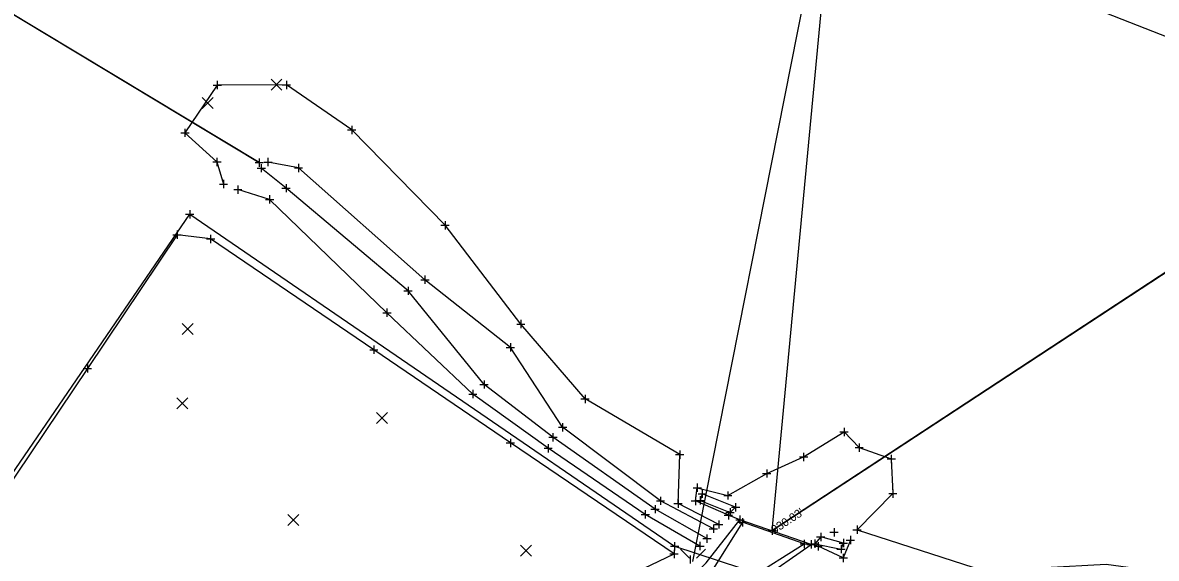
# Model space of a CAD drawing. Extents: x 2331247 to 2333939, y 279314 to 282014.
# Drawn here: x 2332516.5 to 2332654, y 280471.6 to 280536.5 of the extents above; entities that cross this region are included whole.
import ezdxf

# ---------------------------------------------------------------- set-up
doc = ezdxf.new("R2010")
doc.units = 0
for name, color, linetype in [('DR_X_Drive_Pipe', 7, 'Continuous'), ('DR_X_Headwall', 7, 'Continuous'), ('DR_X_Storm_Sewer', 7, 'Continuous'), ('HY_X_Water_Edge', 7, 'Continuous'), ('RD_X_Fence', 7, 'Continuous'), ('SC_Scratch1', 7, 'Continuous'), ('Stream 1', 7, 'Continuous'), ('SV_Observation', 7, 'Continuous'), ('SV_X_Break_Lines', 7, 'Continuous'), ('SV_X_Control_Cells_Found', 7, 'Continuous'), ('SV_X_Random_Point', 7, 'Continuous'), ('UT_X_Overhead_Telecom', 7, 'Continuous')]:
    doc.layers.add(name, color=color, linetype=linetype)

msp = doc.modelspace()

# ---------------------------------------------------------------- linework, layer by layer
msp.add_lwpolyline([(2332817.33, 280612.66), (2332607.42, 280474.92)])
at = {"layer": 'DR_X_Drive_Pipe'}
msp.add_lwpolyline([(2332545.21, 280519.51), (2332447.92, 280578.06)], dxfattribs=at)
at = {"layer": 'DR_X_Headwall'}
for points in [[(2332602.98, 280477.75), (2332598.92, 280479.38), (2332598.67, 280478.58), (2332602.3, 280477.12)], [(2332615.76, 280472.68), (2332616.05, 280473.41), (2332613.3, 280474.15), (2332612.59, 280473.32)]]:
    msp.add_lwpolyline(points, close=True, dxfattribs=at)
at = {"layer": 'DR_X_Storm_Sewer'}
for p, q in [((2332607.42, 280474.92), (2332817.33, 280612.66)), ((2332447.92, 280578.06), (2332545.21, 280519.51))]:
    msp.add_line(p, q, dxfattribs=at)
at = {"layer": 'HY_X_Water_Edge'}
for points in [[(2332363.34, 280175.46), (2332389.42, 280200.76), (2332413.43, 280199.51), (2332417.58, 280206.07), (2332416.16, 280218.98), (2332423.66, 280245.69), (2332431.91, 280271.77), (2332444.8, 280293.01), (2332458.58, 280309.27), (2332481.85, 280326.75), (2332494.02, 280345.7), (2332502.42, 280362.31), (2332517.37, 280370.05), (2332526.14, 280366.88), (2332534.75, 280384.03), (2332544.11, 280395.57), (2332549.43, 280417.73), (2332557.29, 280431.22), (2332566.01, 280443.67), (2332582.71, 280453.54), (2332593.15, 280464.65), (2332599.39, 280471.03), (2332603.51, 280476.23)], [(2332394.74, 280194.82), (2332415.54, 280196.86), (2332423.02, 280200.68), (2332423.85, 280205.22), (2332421.05, 280220.72), (2332429.21, 280245.01), (2332436.82, 280271.58), (2332449.74, 280290.96), (2332464.91, 280306.08), (2332482.64, 280321.13), (2332499.76, 280345.28), (2332505.68, 280360.47), (2332506.64, 280362.04), (2332519.58, 280364.48), (2332528.79, 280364.13), (2332536.96, 280380.5), (2332548.69, 280396.62), (2332555.94, 280412.9), (2332564.08, 280431.96), (2332575.6, 280441.74), (2332591.29, 280450.67), (2332604.28, 280463.06), (2332605.89, 280468.85), (2332612.13, 280473.25)]]:
    msp.add_lwpolyline(points, dxfattribs=at)
at = {"layer": 'RD_X_Fence'}
msp.add_lwpolyline([(2332471.27, 280418.89), (2332503.51, 280464.65), (2332536.8, 280513.25), (2332595.58, 280473.01), (2332611.71, 280467.72), (2332629.37, 280467.72), (2332688.32, 280457.09), (2332754.9, 280426.71), (2332807.86, 280397.34), (2332857.71, 280364.51), (2332902.55, 280327.37), (2332945.19, 280285.57), (2332980.98, 280237.15), (2333013.15, 280194.42), (2333002.94, 280179.22), (2332931.31, 280144.84)], dxfattribs=at)
at = {"layer": 'SC_Scratch1'}
for p, q in [((2332607.42, 280475.42), (2332607.42, 280474.42)), ((2332606.92, 280474.92), (2332607.92, 280474.92)), ((2332607.42, 280474.92), (2332607.42, 280474.92))]:
    msp.add_line(p, q, dxfattribs=at)
at = {"layer": 'Stream 1'}
for p, q in [((2332539.64, 280528.91), (2332540.64, 280528.91)), ((2332540.14, 280529.41), (2332540.14, 280528.41)), ((2332540.14, 280528.91), (2332540.14, 280528.91)), ((2332548.02, 280528.92), (2332549.02, 280528.92)), ((2332548.52, 280529.42), (2332548.52, 280528.42)), ((2332548.52, 280528.92), (2332548.52, 280528.92)), ((2332536.21, 280523.62), (2332536.21, 280522.62)), ((2332555.93, 280523.47), (2332556.93, 280523.47)), ((2332556.43, 280523.97), (2332556.43, 280522.97)), ((2332556.43, 280523.47), (2332556.43, 280523.47)), ((2332535.71, 280523.12), (2332536.71, 280523.12)), ((2332536.21, 280523.12), (2332536.21, 280523.12)), ((2332539.59, 280519.59), (2332540.59, 280519.59)), ((2332540.09, 280520.09), (2332540.09, 280519.09)), ((2332540.09, 280519.59), (2332540.09, 280519.59)), ((2332544.71, 280519.51), (2332545.71, 280519.51)), ((2332545.21, 280520.01), (2332545.21, 280519.01)), ((2332545.21, 280519.51), (2332545.21, 280519.51)), ((2332545.47, 280519.34), (2332545.47, 280518.34)), ((2332545.78, 280519.58), (2332546.78, 280519.58)), ((2332546.28, 280520.08), (2332546.28, 280519.08)), ((2332546.28, 280519.58), (2332546.28, 280519.58)), ((2332549.98, 280519.37), (2332549.98, 280518.37)), ((2332544.97, 280518.84), (2332545.97, 280518.84)), ((2332545.47, 280518.84), (2332545.47, 280518.84)), ((2332549.48, 280518.87), (2332550.48, 280518.87)), ((2332549.98, 280518.87), (2332549.98, 280518.87)), ((2332540.39, 280516.92), (2332541.39, 280516.92)), ((2332540.89, 280517.42), (2332540.89, 280516.42)), ((2332540.89, 280516.92), (2332540.89, 280516.92)), ((2332542.63, 280516.74), (2332542.63, 280515.74)), ((2332548.47, 280516.92), (2332548.47, 280515.92)), ((2332542.13, 280516.24), (2332543.13, 280516.24)), ((2332542.63, 280516.24), (2332542.63, 280516.24)), ((2332546.48, 280515.55), (2332546.48, 280514.55)), ((2332547.97, 280516.42), (2332548.97, 280516.42)), ((2332548.47, 280516.42), (2332548.47, 280516.42)), ((2332545.98, 280515.05), (2332546.98, 280515.05)), ((2332546.48, 280515.05), (2332546.48, 280515.05)), ((2332536.3, 280513.25), (2332537.3, 280513.25)), ((2332536.8, 280513.75), (2332536.8, 280512.75)), ((2332536.8, 280513.25), (2332536.8, 280513.25)), ((2332567.75, 280512.42), (2332567.75, 280511.42)), ((2332535.26, 280511.27), (2332535.26, 280510.27)), ((2332567.25, 280511.92), (2332568.25, 280511.92)), ((2332567.75, 280511.92), (2332567.75, 280511.92)), ((2332534.76, 280510.77), (2332535.76, 280510.77)), ((2332535.26, 280510.77), (2332535.26, 280510.77)), ((2332538.83, 280510.27), (2332539.83, 280510.27)), ((2332539.33, 280510.77), (2332539.33, 280509.77)), ((2332539.33, 280510.27), (2332539.33, 280510.27)), ((2332565.31, 280505.82), (2332565.31, 280504.82)), ((2332563.26, 280504.47), (2332563.26, 280503.47)), ((2332564.81, 280505.32), (2332565.81, 280505.32)), ((2332565.31, 280505.32), (2332565.31, 280505.32)), ((2332562.76, 280503.97), (2332563.76, 280503.97)), ((2332563.26, 280503.97), (2332563.26, 280503.97)), ((2332560.7, 280501.82), (2332560.7, 280500.82)), ((2332560.2, 280501.32), (2332561.2, 280501.32)), ((2332560.7, 280501.32), (2332560.7, 280501.32)), ((2332576.94, 280500.45), (2332576.94, 280499.45)), ((2332576.44, 280499.95), (2332577.44, 280499.95)), ((2332576.94, 280499.95), (2332576.94, 280499.95)), ((2332559.12, 280497.33), (2332559.12, 280496.33)), ((2332575.67, 280497.62), (2332575.67, 280496.62)), ((2332558.62, 280496.83), (2332559.62, 280496.83)), ((2332559.12, 280496.83), (2332559.12, 280496.83)), ((2332575.17, 280497.12), (2332576.17, 280497.12)), ((2332575.67, 280497.12), (2332575.67, 280497.12)), ((2332523.89, 280494.56), (2332524.89, 280494.56)), ((2332524.39, 280495.06), (2332524.39, 280494.06)), ((2332524.39, 280494.56), (2332524.39, 280494.56)), ((2332571.12, 280491.97), (2332571.12, 280490.97)), ((2332571.98, 280492.62), (2332572.98, 280492.62)), ((2332572.48, 280493.12), (2332572.48, 280492.12)), ((2332572.48, 280492.62), (2332572.48, 280492.62)), ((2332570.62, 280491.47), (2332571.62, 280491.47)), ((2332571.12, 280491.47), (2332571.12, 280491.47)), ((2332584.22, 280490.87), (2332585.22, 280490.87)), ((2332584.72, 280491.37), (2332584.72, 280490.37)), ((2332584.72, 280490.87), (2332584.72, 280490.87)), ((2332582.01, 280487.94), (2332582.01, 280486.94)), ((2332580.83, 280486.73), (2332580.83, 280485.73)), ((2332581.51, 280487.44), (2332582.51, 280487.44)), ((2332582.01, 280487.44), (2332582.01, 280487.44)), ((2332615.63, 280486.87), (2332616.63, 280486.87)), ((2332616.13, 280487.37), (2332616.13, 280486.37)), ((2332616.13, 280486.87), (2332616.13, 280486.87)), ((2332575.17, 280485.54), (2332576.17, 280485.54)), ((2332575.67, 280486.04), (2332575.67, 280485.04)), ((2332575.67, 280485.54), (2332575.67, 280485.54)), ((2332580.25, 280485.4), (2332580.25, 280484.4)), ((2332580.33, 280486.23), (2332581.33, 280486.23)), ((2332580.83, 280486.23), (2332580.83, 280486.23)), ((2332617.46, 280484.97), (2332618.46, 280484.97)), ((2332617.96, 280485.47), (2332617.96, 280484.47)), ((2332617.96, 280484.97), (2332617.96, 280484.97)), ((2332579.75, 280484.9), (2332580.75, 280484.9)), ((2332580.25, 280484.9), (2332580.25, 280484.9)), ((2332595.7, 280484.13), (2332596.7, 280484.13)), ((2332596.2, 280484.63), (2332596.2, 280483.63)), ((2332596.2, 280484.13), (2332596.2, 280484.13)), ((2332610.73, 280483.84), (2332611.73, 280483.84)), ((2332611.23, 280484.34), (2332611.23, 280483.34)), ((2332611.23, 280483.84), (2332611.23, 280483.84)), ((2332621.36, 280483.6), (2332622.36, 280483.6)), ((2332621.86, 280484.1), (2332621.86, 280483.1)), ((2332621.86, 280483.6), (2332621.86, 280483.6)), ((2332606.75, 280482.34), (2332606.75, 280481.34)), ((2332606.25, 280481.84), (2332607.25, 280481.84)), ((2332606.75, 280481.84), (2332606.75, 280481.84)), ((2332597.83, 280480.11), (2332598.83, 280480.11)), ((2332598.33, 280480.61), (2332598.33, 280479.61)), ((2332598.33, 280480.11), (2332598.33, 280480.11)), ((2332598.92, 280479.88), (2332598.92, 280478.88)), ((2332602.04, 280479.67), (2332602.04, 280478.67)), ((2332622.04, 280479.9), (2332622.04, 280478.9)), ((2332593.37, 280478.52), (2332594.37, 280478.52)), ((2332593.87, 280479.02), (2332593.87, 280478.02)), ((2332593.87, 280478.52), (2332593.87, 280478.52)), ((2332595.5, 280478.19), (2332596.5, 280478.19)), ((2332596, 280478.69), (2332596, 280477.69)), ((2332596, 280478.19), (2332596, 280478.19)), ((2332597.61, 280478.51), (2332598.61, 280478.51)), ((2332598.11, 280479.01), (2332598.11, 280478.01)), ((2332598.11, 280478.51), (2332598.11, 280478.51)), ((2332598.17, 280478.58), (2332599.17, 280478.58)), ((2332598.42, 280479.38), (2332599.42, 280479.38)), ((2332598.67, 280479.08), (2332598.67, 280478.08)), ((2332598.67, 280478.58), (2332598.67, 280478.58)), ((2332598.92, 280479.38), (2332598.92, 280479.38)), ((2332601.54, 280479.17), (2332602.54, 280479.17)), ((2332602.04, 280479.17), (2332602.04, 280479.17)), ((2332602.98, 280478.25), (2332602.98, 280477.25)), ((2332621.54, 280479.4), (2332622.54, 280479.4)), ((2332622.04, 280479.4), (2332622.04, 280479.4)), ((2332591.53, 280476.88), (2332592.53, 280476.88)), ((2332592.03, 280477.38), (2332592.03, 280476.38)), ((2332592.03, 280476.88), (2332592.03, 280476.88)), ((2332592.71, 280477.51), (2332593.71, 280477.51)), ((2332593.21, 280478.01), (2332593.21, 280477.01)), ((2332593.21, 280477.51), (2332593.21, 280477.51)), ((2332601.61, 280476.78), (2332602.61, 280476.78)), ((2332601.8, 280477.12), (2332602.8, 280477.12)), ((2332602.11, 280477.28), (2332602.11, 280476.28)), ((2332602.11, 280476.78), (2332602.11, 280476.78)), ((2332602.3, 280477.62), (2332602.3, 280476.62)), ((2332602.3, 280477.12), (2332602.3, 280477.12)), ((2332602.48, 280477.75), (2332603.48, 280477.75)), ((2332602.98, 280477.75), (2332602.98, 280477.75)), ((2332603.51, 280476.73), (2332603.51, 280475.73)), ((2332600.28, 280475.64), (2332600.28, 280474.64)), ((2332600.43, 280475.66), (2332601.43, 280475.66)), ((2332600.93, 280476.16), (2332600.93, 280475.16)), ((2332600.93, 280475.66), (2332600.93, 280475.66)), ((2332603.01, 280476.23), (2332604.01, 280476.23)), ((2332603.31, 280475.92), (2332604.31, 280475.92)), ((2332603.51, 280476.23), (2332603.51, 280476.23)), ((2332603.81, 280476.42), (2332603.81, 280475.42)), ((2332603.81, 280475.92), (2332603.81, 280475.92)), ((2332617.7, 280475.52), (2332617.7, 280474.52)), ((2332599.01, 280473.95), (2332600.01, 280473.95)), ((2332599.51, 280474.45), (2332599.51, 280473.45)), ((2332599.51, 280473.95), (2332599.51, 280473.95)), ((2332599.78, 280475.14), (2332600.78, 280475.14)), ((2332600.28, 280475.14), (2332600.28, 280475.14)), ((2332612.8, 280474.15), (2332613.8, 280474.15)), ((2332613.3, 280474.65), (2332613.3, 280473.65)), ((2332613.3, 280474.15), (2332613.3, 280474.15)), ((2332614.42, 280474.72), (2332615.42, 280474.72)), ((2332614.92, 280475.22), (2332614.92, 280474.22)), ((2332614.92, 280474.72), (2332614.92, 280474.72)), ((2332616.05, 280473.91), (2332616.05, 280472.91)), ((2332616.89, 280474.27), (2332616.89, 280473.27)), ((2332617.2, 280475.02), (2332618.2, 280475.02)), ((2332617.7, 280475.02), (2332617.7, 280475.02)), ((2332595.08, 280473.01), (2332596.08, 280473.01)), ((2332595.52, 280472.59), (2332595.52, 280471.59)), ((2332595.58, 280473.51), (2332595.58, 280472.51)), ((2332595.58, 280473.01), (2332595.58, 280473.01)), ((2332598.16, 280473.04), (2332599.16, 280473.04)), ((2332598.66, 280473.54), (2332598.66, 280472.54)), ((2332598.66, 280473.04), (2332598.66, 280473.04)), ((2332610.79, 280473.3), (2332611.79, 280473.3)), ((2332611.29, 280473.8), (2332611.29, 280472.8)), ((2332611.29, 280473.3), (2332611.29, 280473.3)), ((2332611.63, 280473.25), (2332612.63, 280473.25)), ((2332612.09, 280473.32), (2332613.09, 280473.32)), ((2332612.13, 280473.75), (2332612.13, 280472.75)), ((2332612.13, 280473.25), (2332612.13, 280473.25)), ((2332612.49, 280473.02), (2332613.49, 280473.02)), ((2332612.59, 280473.82), (2332612.59, 280472.82)), ((2332612.59, 280473.32), (2332612.59, 280473.32)), ((2332612.99, 280473.52), (2332612.99, 280472.52)), ((2332612.99, 280473.02), (2332612.99, 280473.02)), ((2332615.26, 280472.68), (2332616.26, 280472.68)), ((2332615.55, 280473.41), (2332616.55, 280473.41)), ((2332615.76, 280473.18), (2332615.76, 280472.18)), ((2332615.76, 280472.68), (2332615.76, 280472.68)), ((2332616.05, 280473.41), (2332616.05, 280473.41)), ((2332616.39, 280473.77), (2332617.39, 280473.77)), ((2332616.89, 280473.77), (2332616.89, 280473.77)), ((2332595.02, 280472.09), (2332596.02, 280472.09)), ((2332595.52, 280472.09), (2332595.52, 280472.09)), ((2332597.47, 280471.91), (2332597.47, 280470.91)), ((2332615.53, 280471.61), (2332616.53, 280471.61)), ((2332616.03, 280472.11), (2332616.03, 280471.11)), ((2332616.03, 280471.61), (2332616.03, 280471.61))]:
    msp.add_line(p, q, dxfattribs=at)
at = {"layer": 'SV_Observation'}
for p in [(2332597.8, 280471.17), (2332607.42, 280474.92)]:
    msp.add_line(p, (2332615.53, 280560.63), dxfattribs=at)
at = {"layer": 'SV_X_Break_Lines'}
for points in [[(2332600.93, 280475.66), (2332596, 280478.19), (2332596.2, 280484.13), (2332584.72, 280490.87), (2332576.94, 280499.95), (2332567.75, 280511.92), (2332556.43, 280523.47), (2332548.52, 280528.92), (2332540.14, 280528.91), (2332536.21, 280523.12), (2332540.09, 280519.59), (2332540.89, 280516.92)], [(2332600.28, 280475.14), (2332593.87, 280478.52), (2332582.01, 280487.44), (2332575.67, 280497.12), (2332565.31, 280505.32), (2332549.98, 280518.87), (2332546.28, 280519.58)], [(2332599.51, 280473.95), (2332593.21, 280477.51), (2332580.83, 280486.23), (2332572.48, 280492.62), (2332563.26, 280503.97), (2332548.47, 280516.42), (2332545.47, 280518.84)], [(2332598.66, 280473.04), (2332592.03, 280476.88), (2332580.25, 280484.9), (2332571.12, 280491.47), (2332560.7, 280501.32), (2332546.48, 280515.05), (2332542.63, 280516.24)], [(2332490.07, 280356.61), (2332496.61, 280366.64), (2332531.85, 280411.22), (2332542.52, 280423.44), (2332554.14, 280437.04), (2332563.39, 280446.89), (2332573.43, 280455.89), (2332581.66, 280460.13), (2332580.9, 280465.12), (2332595.52, 280472.09), (2332575.67, 280485.54), (2332559.12, 280496.83), (2332539.33, 280510.27), (2332535.26, 280510.77), (2332524.39, 280494.56), (2332508.81, 280471.4), (2332491.31, 280445.61), (2332478.44, 280427.4)], [(2332612.99, 280473.02), (2332612.13, 280473.25), (2332603.51, 280476.23), (2332602.11, 280476.78), (2332598.11, 280478.51), (2332598.33, 280480.11), (2332602.04, 280479.17), (2332606.75, 280481.84), (2332611.23, 280483.84), (2332616.13, 280486.87), (2332617.96, 280484.97), (2332621.86, 280483.6), (2332622.04, 280479.4), (2332617.7, 280475.02), (2332633.12, 280470.04), (2332647.91, 280470.83), (2332665.65, 280468.41)], [(2332536.84, 280381.28), (2332548.1, 280396.91), (2332552.36, 280407.18), (2332554.61, 280413.48), (2332563.08, 280432.24), (2332574.96, 280442.67), (2332590.44, 280452.12), (2332602.42, 280463.9), (2332604.64, 280469.1), (2332611.29, 280473.3), (2332603.81, 280475.92), (2332600.05, 280469.98), (2332594.25, 280463.78), (2332583.8, 280452.84), (2332567.04, 280442.27), (2332558.4, 280430.63), (2332550.52, 280417.34), (2332545.31, 280395.59), (2332535.84, 280383.52)], [(2332616.89, 280473.77), (2332616.03, 280471.61), (2332612.99, 280473.02)]]:
    msp.add_lwpolyline(points, dxfattribs=at)
at = {"layer": 'SV_X_Control_Cells_Found'}
for p, q in [((2332596.29, 280472.67), (2332597.38, 280471.58)), ((2332598.22, 280471.58), (2332599.31, 280472.67))]:
    msp.add_line(p, q, dxfattribs=at)
at = {"layer": 'SV_X_Random_Point'}
for p, q in [((2332546.65, 280528.28), (2332547.98, 280529.62)), ((2332546.65, 280529.62), (2332547.98, 280528.28)), ((2332538.31, 280526.07), (2332539.64, 280527.4)), ((2332538.31, 280527.4), (2332539.64, 280526.07)), ((2332535.87, 280498.67), (2332537.21, 280500.01)), ((2332535.87, 280500.01), (2332537.21, 280498.67)), ((2332535.23, 280489.66), (2332536.56, 280491)), ((2332535.23, 280491), (2332536.56, 280489.66)), ((2332559.43, 280487.91), (2332560.76, 280489.24)), ((2332559.43, 280489.24), (2332560.76, 280487.91)), ((2332548.68, 280475.54), (2332550.02, 280476.88)), ((2332548.68, 280476.88), (2332550.02, 280475.54)), ((2332576.88, 280471.8), (2332578.22, 280473.14)), ((2332576.88, 280473.14), (2332578.22, 280471.8))]:
    msp.add_line(p, q, dxfattribs=at)
at = {"layer": 'UT_X_Overhead_Telecom'}
msp.add_lwpolyline([(2332474.12, 280605.71), (2332735.57, 280503.33), (2332947.92, 280387.93), (2333091.98, 280195.88)], dxfattribs=at)

# ---------------------------------------------------------------- texts
at = {"layer": 'SC_Scratch1'}
msp.add_text("930.03'", height=1, rotation=33.2733, dxfattribs=at).set_placement((2332607.7, 280474.5))

doc.saveas('drawing.dxf')
